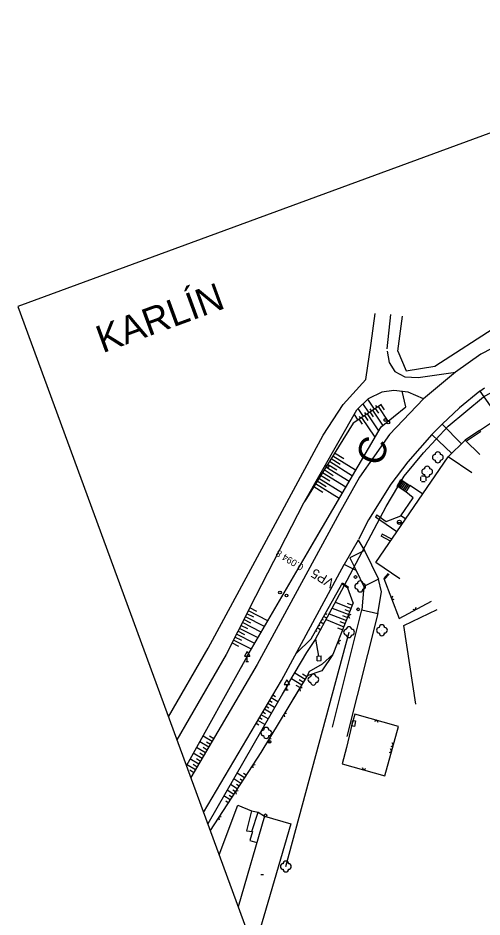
# Model space of a CAD drawing. Extents: x -574526 to -573537, y -1188297 to -1187280.
# Drawn here: x -574525.7 to -574440.8, y -1188129.5 to -1187965.1 of the extents above; entities that cross this region are included whole.
import ezdxf

# ---------------------------------------------------------------- set-up
doc = ezdxf.new("R2010")
doc.units = 0
for name, color, linetype in [('Vrstva 10', 7, 'Continuous'), ('Vrstva 13', 7, 'Continuous'), ('Vrstva 14', 7, 'Continuous'), ('Vrstva 16', 7, 'Continuous'), ('Vrstva 18', 7, 'Continuous'), ('Vrstva 19', 7, 'Continuous'), ('Vrstva 2', 7, 'Continuous'), ('Vrstva 21', 7, 'Continuous'), ('Vrstva 4', 7, 'Continuous'), ('Vrstva 5', 7, 'Continuous'), ('Vrstva 6', 7, 'Continuous'), ('Vrstva 63', 7, 'Continuous'), ('Vrstva 7', 7, 'Continuous'), ('Vrstva 8', 7, 'Continuous'), ('Vrstva 9', 7, 'Continuous')]:
    doc.layers.add(name, color=color, linetype=linetype)

# ---------------------------------------------------------------- blocks, each defined once
blk = doc.blocks.new('8$110')
at = {"layer": 'Vrstva 6'}
blk.add_line((-0.75, 0), (0.75, 0), dxfattribs=at)
blk.add_circle((0, 0), 0.75, dxfattribs=at)
blk = doc.blocks.new('3$130')
at = {"layer": 'Vrstva 8'}
blk.add_circle((0, 0), 0.001, dxfattribs=at)
for centre, start, end in [((-1, 0), 90, 270), ((0, 1), 0, 180), ((1, 0), 270, 90), ((0, -1), 180, 0)]:
    blk.add_arc(centre, 1, start, end, dxfattribs=at)
blk = doc.blocks.new('4$030')
at = {"layer": 'Vrstva 5'}
blk.add_line((-0.502, -0.008), (0.498, -0.008), dxfattribs=at)
blk = doc.blocks.new('5$270')
at = {"layer": 'Vrstva 6'}
for p, q in [((0, 3.732), (-1, 2)), ((0, 3.732), (1, 2)), ((-1, 2), (1, 2)), ((-0.5, 0), (0.5, 0)), ((0, 0), (0, 2))]:
    blk.add_line(p, q, dxfattribs=at)
blk = doc.blocks.new('6$010')
at = {"layer": 'Vrstva 21'}
blk.add_circle((0, 0), 0.5, dxfattribs=at)
blk = doc.blocks.new('6$091')
at = {"layer": 'Vrstva 21'}
for p, q in [((-1, 0.7), (-1, -0.7)), ((0.7, 1), (-0.7, 1)), ((1, -0.7), (1, 0.7)), ((-0.7, -1), (0.7, -1))]:
    blk.add_line(p, q, dxfattribs=at)
blk = doc.blocks.new('200')
at = {"layer": 'Vrstva 63'}
blk.add_lwpolyline([(0, 0), (210, 0), (210, 297), (0, 297), (0, 0)], close=True, dxfattribs=at)

msp = doc.modelspace()

# ---------------------------------------------------------------- linework, layer by layer
at = {"layer": 'Vrstva 10'}
for p, q in [((-574454.79, -1188036.24), (-574455.46, -1188033.34)), ((-574459.24, -1188035.78), (-574464.41, -1188039.22)), ((-574462.72, -1188035.6), (-574461.57, -1188037.33)), ((-574461.78, -1188034.84), (-574460.57, -1188036.66)), ((-574460.35, -1188035.9), (-574460.07, -1188036.33)), ((-574458.03, -1188038.83), (-574459.81, -1188036.16)), ((-574458.7, -1188036.74), (-574459.31, -1188035.82)), ((-574464.26, -1188037.61), (-574463.57, -1188038.66)), ((-574463.56, -1188036.49), (-574462.57, -1188037.99)), ((-574462.35, -1188037.23), (-574462.07, -1188037.66)), ((-574461.7, -1188038.73), (-574462.31, -1188037.82)), ((-574459.74, -1188040.59), (-574461.81, -1188037.49)), ((-574461.35, -1188036.57), (-574461.07, -1188036.99)), ((-574460.7, -1188038.07), (-574461.31, -1188037.15)), ((-574458.97, -1188039.58), (-574460.81, -1188036.82)), ((-574459.7, -1188037.4), (-574460.31, -1188036.49)), ((-574459.32, -1188039.86), (-574454.79, -1188036.24)), ((-574464.41, -1188039.22), (-574473.28, -1188053.46)), ((-574463.35, -1188037.9), (-574463.06, -1188038.33)), ((-574462.69, -1188039.4), (-574463.3, -1188038.49)), ((-574460.42, -1188041.74), (-574462.81, -1188038.15)), ((-574472.34, -1188062.16), (-574459.32, -1188039.86)), ((-574466.79, -1188046.77), (-574468.46, -1188045.72)), ((-574463.97, -1188047.82), (-574468.15, -1188045.21)), ((-574466.15, -1188045.75), (-574467.83, -1188044.71)), ((-574465.18, -1188049.89), (-574469.41, -1188047.25)), ((-574467.42, -1188047.79), (-574469.1, -1188046.74)), ((-574464.57, -1188048.86), (-574468.78, -1188046.23)), ((-574466.39, -1188051.97), (-574470.68, -1188049.29)), ((-574468.69, -1188049.82), (-574470.37, -1188048.78)), ((-574465.78, -1188050.93), (-574470.05, -1188048.27)), ((-574468.06, -1188048.8), (-574469.73, -1188047.76)), ((-574469.96, -1188051.86), (-574471.63, -1188050.82)), ((-574466.99, -1188053), (-574471.32, -1188050.31)), ((-574469.33, -1188050.84), (-574471, -1188049.8)), ((-574483.31, -1188072.98), (-574473.46, -1188053.77)), ((-574472.34, -1188062.16), (-574470.39, -1188058.82)), ((-574483.86, -1188081.95), (-574472.34, -1188062.16)), ((-574483.86, -1188081.95), (-574472.34, -1188062.16)), ((-574472.11, -1188078.6), (-574466.48, -1188068.63)), ((-574471.33, -1188078.7), (-574466.04, -1188068.94)), ((-574464.39, -1188072.03), (-574465.38, -1188069.39)), ((-574467.66, -1188071.93), (-574464.79, -1188073.06)), ((-574465.51, -1188072.13), (-574464.57, -1188072.5)), ((-574483.31, -1188072.98), (-574487.68, -1188081.5)), ((-574480.02, -1188075.35), (-574483.59, -1188073.52)), ((-574482.07, -1188073.62), (-574483.31, -1188072.98)), ((-574482.07, -1188073.62), (-574483.31, -1188072.98)), ((-574468.24, -1188073), (-574465.23, -1188074.18)), ((-574465.95, -1188073.25), (-574465.01, -1188073.62)), ((-574483.17, -1188075.75), (-574484.41, -1188075.12)), ((-574483.17, -1188075.75), (-574484.41, -1188075.12)), ((-574480.62, -1188076.39), (-574484.13, -1188074.58)), ((-574482.62, -1188074.69), (-574483.86, -1188074.05)), ((-574482.62, -1188074.69), (-574483.86, -1188074.05)), ((-574469.8, -1188075.93), (-574470.41, -1188075.59)), ((-574469.85, -1188075.21), (-574470.11, -1188075.07)), ((-574469.25, -1188074.86), (-574469.82, -1188074.54)), ((-574469.26, -1188074.17), (-574469.52, -1188074.02)), ((-574469.39, -1188075.12), (-574466.11, -1188076.41)), ((-574468.81, -1188074.06), (-574465.67, -1188075.29)), ((-574466.83, -1188075.48), (-574465.89, -1188075.85)), ((-574466.39, -1188074.37), (-574465.45, -1188074.73)), ((-574484.26, -1188077.89), (-574485.5, -1188077.25)), ((-574484.26, -1188077.89), (-574485.5, -1188077.25)), ((-574481.83, -1188078.46), (-574485.23, -1188076.72)), ((-574483.71, -1188076.82), (-574484.95, -1188076.19)), ((-574483.71, -1188076.82), (-574484.95, -1188076.19)), ((-574481.23, -1188077.42), (-574484.68, -1188075.65)), ((-574471.03, -1188077.3), (-574471.3, -1188077.15)), ((-574470.39, -1188076.97), (-574471, -1188076.63)), ((-574470.44, -1188076.26), (-574470.71, -1188076.11)), ((-574467.27, -1188076.6), (-574466.33, -1188076.97)), ((-574483.04, -1188080.54), (-574486.32, -1188078.86)), ((-574484.81, -1188078.96), (-574486.05, -1188078.32)), ((-574484.81, -1188078.96), (-574486.05, -1188078.32)), ((-574482.43, -1188079.5), (-574485.78, -1188077.79)), ((-574472.11, -1188078.6), (-574474.8, -1188081.24)), ((-574472.91, -1188081.13), (-574471.32, -1188078.73)), ((-574472.91, -1188081.13), (-574471.32, -1188078.73)), ((-574471.33, -1188078.7), (-574470.79, -1188081.77)), ((-574485.36, -1188080.02), (-574486.6, -1188079.39)), ((-574487.68, -1188081.5), (-574496.66, -1188097.11)), ((-574483.86, -1188081.95), (-574494.94, -1188101.79)), ((-574483.86, -1188081.95), (-574484.91, -1188083.83)), ((-574476.2, -1188086.67), (-574472.91, -1188081.13)), ((-574470.06, -1188083.2), (-574468.12, -1188081.52)), ((-574472.47, -1188084.63), (-574470.06, -1188083.2)), ((-574475.12, -1188084.85), (-574473.21, -1188086.01)), ((-574475.12, -1188084.85), (-574473.21, -1188086.01)), ((-574473.67, -1188085.03), (-574472.9, -1188085.5)), ((-574473.67, -1188085.03), (-574472.9, -1188085.5)), ((-574472.47, -1188084.63), (-574472.86, -1188085.44)), ((-574472.47, -1188084.63), (-574472.86, -1188085.44)), ((-574476.2, -1188086.67), (-574491.03, -1188112.44)), ((-574476.2, -1188086.67), (-574477.4, -1188088.75)), ((-574475.73, -1188085.89), (-574473.83, -1188087.04)), ((-574475.73, -1188085.89), (-574473.83, -1188087.04)), ((-574474.91, -1188087.09), (-574474.14, -1188087.55)), ((-574474.91, -1188087.09), (-574474.14, -1188087.55)), ((-574474.29, -1188086.06), (-574473.52, -1188086.53)), ((-574474.29, -1188086.06), (-574473.52, -1188086.53)), ((-574479.22, -1188090.25), (-574479.72, -1188089.96)), ((-574478.21, -1188090.16), (-574479.42, -1188089.44)), ((-574478.61, -1188089.22), (-574479.11, -1188088.93)), ((-574480.44, -1188092.32), (-574480.94, -1188092.03)), ((-574479.41, -1188092.24), (-574480.64, -1188091.51)), ((-574479.83, -1188091.29), (-574480.33, -1188090.99)), ((-574478.81, -1188091.2), (-574480.03, -1188090.48)), ((-574480.6, -1188094.32), (-574481.86, -1188093.58)), ((-574481.05, -1188093.35), (-574481.55, -1188093.06)), ((-574480, -1188093.28), (-574481.25, -1188092.54)), ((-574481.66, -1188094.39), (-574482.16, -1188094.09)), ((-574491.88, -1188096.38), (-574490.23, -1188097.35)), ((-574490.68, -1188096.39), (-574489.93, -1188096.83)), ((-574493.09, -1188098.45), (-574491.45, -1188099.42)), ((-574492.48, -1188097.42), (-574490.84, -1188098.38)), ((-574491.89, -1188098.46), (-574491.14, -1188098.9)), ((-574491.28, -1188097.43), (-574490.53, -1188097.87)), ((-574493.7, -1188099.49), (-574492.05, -1188100.45)), ((-574492.5, -1188099.5), (-574491.75, -1188099.94)), ((-574494.91, -1188101.56), (-574493.27, -1188102.52)), ((-574494.31, -1188100.52), (-574492.66, -1188101.49)), ((-574493.71, -1188101.57), (-574492.96, -1188102.01)), ((-574493.11, -1188100.53), (-574492.36, -1188100.97)), ((-574494.32, -1188102.6), (-574493.57, -1188103.04)), ((-574485.67, -1188103.13), (-574484.32, -1188104)), ((-574484.47, -1188103.19), (-574484, -1188103.5)), ((-574486.87, -1188105.21), (-574485.63, -1188106.01)), ((-574486.27, -1188104.17), (-574484.98, -1188105.01)), ((-574485.77, -1188105.2), (-574485.3, -1188105.51)), ((-574485.12, -1188104.2), (-574484.65, -1188104.5)), ((-574487.47, -1188106.25), (-574486.28, -1188107.02)), ((-574486.43, -1188106.21), (-574485.96, -1188106.52)), ((-574488.07, -1188107.29), (-574486.94, -1188108.03)), ((-574487.73, -1188108.22), (-574487.26, -1188108.53)), ((-574487.08, -1188107.22), (-574486.61, -1188107.52))]:
    msp.add_line(p, q, dxfattribs=at)
at = {"layer": 'Vrstva 16'}
for p, q in [((-574464.67, -1188094.54), (-574464.46, -1188093.56)), ((-574464.46, -1188093.56), (-574463.98, -1188093.65)), ((-574463.98, -1188093.65), (-574464.17, -1188094.63)), ((-574464.17, -1188094.63), (-574464.67, -1188094.54))]:
    msp.add_line(p, q, dxfattribs=at)
at = {"layer": 'Vrstva 2'}
msp.add_lwpolyline([(-574466.04, -1188068.94), (-574458.4, -1188054.44), (-574455.1, -1188048.91), (-574451.58, -1188044.6), (-574447.05, -1188039.72), (-574440.59, -1188034.41), (-574436.57, -1188032.11), (-574433.45, -1188030.75)], dxfattribs=at)
at = {"layer": 'Vrstva 4'}
for p, q in [((-574456.25, -1188026.01), (-574455.42, -1188019.62)), ((-574449.5, -1188028.77), (-574437.95, -1188021.35)), ((-574490.97, -1188080.36), (-574479.05, -1188058.36)), ((-574455.18, -1188076.22), (-574449.08, -1188073.26)), ((-574452.96, -1188090.57), (-574455.18, -1188076.22)), ((-574476.74, -1188120.25), (-574465.18, -1188077.41)), ((-574498.2, -1188092.91), (-574490.97, -1188080.36))]:
    msp.add_line(p, q, dxfattribs=at)
msp.add_lwpolyline([(-574456.25, -1188026.01), (-574454.72, -1188029.66), (-574449.5, -1188028.77)], dxfattribs=at)
at = {"layer": 'Vrstva 6'}
for p, q in [((-574441.31, -1188040.56), (-574438.57, -1188038.71)), ((-574441.31, -1188040.56), (-574443.92, -1188042.29)), ((-574441.14, -1188040.81), (-574443.7, -1188042.51)), ((-574441.31, -1188040.56), (-574441.14, -1188040.81)), ((-574456.38, -1188050.69), (-574455.68, -1188049.5)), ((-574454.81, -1188051.78), (-574456.38, -1188050.69)), ((-574455.31, -1188049.75), (-574456.1, -1188050.88)), ((-574455.07, -1188049.91), (-574455.86, -1188051.05)), ((-574455.68, -1188049.5), (-574454.05, -1188050.6)), ((-574454.82, -1188050.08), (-574455.61, -1188051.23)), ((-574454.57, -1188050.25), (-574455.36, -1188051.4)), ((-574454.32, -1188050.42), (-574455.12, -1188051.57)), ((-574454.05, -1188050.6), (-574454.81, -1188051.78)), ((-574459.11, -1188059.51), (-574459.29, -1188059.88)), ((-574457.61, -1188060.78), (-574459.29, -1188059.88)), ((-574457.37, -1188060.43), (-574459.11, -1188059.51)), ((-574457.99, -1188066.71), (-574458.83, -1188067.59)), ((-574457.82, -1188066.81), (-574458.68, -1188067.73)), ((-574466.48, -1188068.63), (-574466.37, -1188068.46)), ((-574466.43, -1188068.66), (-574466.48, -1188068.63)), ((-574465.38, -1188069.39), (-574466.43, -1188068.66)), ((-574465.27, -1188069.23), (-574466.37, -1188068.46)), ((-574458.83, -1188067.59), (-574456, -1188074.91)), ((-574458.83, -1188067.59), (-574458.68, -1188067.73)), ((-574465.38, -1188069.39), (-574465.27, -1188069.23)), ((-574464.39, -1188072.03), (-574468.12, -1188081.52)), ((-574456, -1188074.91), (-574450.1, -1188071.73)), ((-574470.98, -1188081.79), (-574470.29, -1188081.73)), ((-574470.98, -1188082.66), (-574470.98, -1188081.79)), ((-574470.29, -1188082.6), (-574470.29, -1188081.73)), ((-574468.12, -1188081.52), (-574470.18, -1188084.45)), ((-574470.98, -1188082.66), (-574470.29, -1188082.6)), ((-574472.83, -1188085.39), (-574481.32, -1188099.38)), ((-574472.83, -1188085.39), (-574475.59, -1188089.93)), ((-574470.18, -1188084.45), (-574472.83, -1188085.39)), ((-574464.09, -1188092.4), (-574464.64, -1188094.38)), ((-574456.1, -1188094.64), (-574464.09, -1188092.4)), ((-574464.64, -1188094.38), (-574465.65, -1188098.5)), ((-574458.61, -1188103.68), (-574456.1, -1188094.64)), ((-574457.99, -1188101.46), (-574456.1, -1188094.64)), ((-574465.65, -1188098.5), (-574466.42, -1188101.49)), ((-574481.32, -1188099.38), (-574490.59, -1188113.65)), ((-574466.42, -1188101.49), (-574458.61, -1188103.68))]:
    msp.add_line(p, q, dxfattribs=at)
for points in [[(-574457.21, -1188070.8), (-574457.42, -1188071.25), (-574456.96, -1188071.45)], [(-574453.52, -1188073.18), (-574453.05, -1188073.32), (-574452.91, -1188072.85)], [(-574464.87, -1188074.2), (-574465.32, -1188074.4), (-574465.12, -1188074.86)], [(-574466.73, -1188078.95), (-574467.19, -1188079.15), (-574466.99, -1188079.6)], [(-574473.76, -1188087.6), (-574474.24, -1188087.72), (-574474.13, -1188088.2)], [(-574473.73, -1188087.54), (-574474.21, -1188087.66), (-574474.09, -1188088.14)], [(-574476.59, -1188092.27), (-574477.08, -1188092.39), (-574476.96, -1188092.87)], [(-574459.85, -1188093.95), (-574460.09, -1188093.52), (-574460.53, -1188093.76)], [(-574479.42, -1188096.93), (-574479.91, -1188097.05), (-574479.79, -1188097.53)], [(-574457.48, -1188098.29), (-574457.05, -1188098.05), (-574457.29, -1188097.62)], [(-574457.79, -1188099.4), (-574457.35, -1188099.16), (-574457.6, -1188098.73)], [(-574482.38, -1188101.65), (-574482.86, -1188101.76), (-574482.76, -1188102.24)], [(-574462.76, -1188102.15), (-574462.52, -1188102.58), (-574462.08, -1188102.34)], [(-574485.47, -1188106.41), (-574485.95, -1188106.51), (-574485.85, -1188107)], [(-574488.56, -1188111.17), (-574489.04, -1188111.27), (-574488.94, -1188111.75)]]:
    msp.add_lwpolyline(points, dxfattribs=at)
at = {"layer": 'Vrstva 7'}
for p, q in [((-574447.01, -1188045.36), (-574443.92, -1188042.29)), ((-574441.27, -1188044.95), (-574443.92, -1188042.29)), ((-574460.27, -1188064.65), (-574447.01, -1188045.36)), ((-574442.73, -1188048.3), (-574447.01, -1188045.36)), ((-574455.89, -1188067.66), (-574460.27, -1188064.65)), ((-574480.65, -1188111.08), (-574485.46, -1188127.6)), ((-574480.65, -1188111.08), (-574475.82, -1188112.43)), ((-574475.82, -1188112.43), (-574481.93, -1188133.39))]:
    msp.add_line(p, q, dxfattribs=at)
at = {"layer": 'Vrstva 9'}
for p, q in [((-574461.11, -1188024.57), (-574460.41, -1188019.13)), ((-574458.19, -1188025.63), (-574457.5, -1188019.35)), ((-574462.1, -1188031.23), (-574461.11, -1188024.57)), ((-574466.25, -1188035.79), (-574462.1, -1188031.23)), ((-574452.54, -1188030.87), (-574445.67, -1188029.88)), ((-574441.24, -1188033.33), (-574440.39, -1188032.74)), ((-574441.24, -1188033.33), (-574438.61, -1188037.07)), ((-574469.93, -1188041.39), (-574466.25, -1188035.79)), ((-574473.46, -1188053.77), (-574463.77, -1188036.75)), ((-574448.16, -1188039.38), (-574450.03, -1188041.26)), ((-574448.16, -1188039.38), (-574444.59, -1188042.95)), ((-574479.05, -1188058.36), (-574469.93, -1188041.39)), ((-574446.38, -1188044.73), (-574450.03, -1188041.26)), ((-574451.71, -1188052.12), (-574454.05, -1188050.6)), ((-574453.46, -1188052.83), (-574454.81, -1188051.78)), ((-574455.71, -1188056.14), (-574453.46, -1188052.83)), ((-574466.91, -1188055.57), (-574482.01, -1188083.33)), ((-574460.06, -1188055.95), (-574460.32, -1188056.36)), ((-574456.42, -1188059.04), (-574460.32, -1188056.36)), ((-574460.06, -1188055.95), (-574458.36, -1188057.15)), ((-574458.36, -1188057.15), (-574455.71, -1188056.14)), ((-574454.87, -1188056.71), (-574455.71, -1188056.14)), ((-574463.53, -1188060.56), (-574466.04, -1188065.03)), ((-574463.53, -1188060.56), (-574462.37, -1188062.48)), ((-574462.37, -1188062.48), (-574465.01, -1188063.82)), ((-574462.37, -1188062.48), (-574459.8, -1188067.75)), ((-574465.01, -1188063.82), (-574463.9, -1188066.15)), ((-574477.51, -1188086.22), (-574466.04, -1188065.03)), ((-574463.9, -1188066.15), (-574466.04, -1188065.03)), ((-574463.9, -1188066.15), (-574462.44, -1188069.09)), ((-574459.8, -1188067.75), (-574462.44, -1188069.09)), ((-574462.44, -1188069.09), (-574462.84, -1188073.31)), ((-574468.2, -1188094.77), (-574462.84, -1188073.31)), ((-574459.91, -1188073.97), (-574465.55, -1188096.51)), ((-574462.84, -1188073.31), (-574459.91, -1188073.97)), ((-574482.01, -1188083.33), (-574494.13, -1188104)), ((-574482.01, -1188083.33), (-574483.02, -1188085.06)), ((-574491.79, -1188110.37), (-574477.51, -1188086.22)), ((-574488.95, -1188118.1), (-574485.53, -1188109.02)), ((-574485.53, -1188109.02), (-574483, -1188110.07)), ((-574483, -1188110.07), (-574483.95, -1188113.71)), ((-574483, -1188110.07), (-574481.81, -1188110.31)), ((-574482.93, -1188113.85), (-574481.81, -1188110.31)), ((-574481.81, -1188110.31), (-574480.65, -1188111.08)), ((-574483.31, -1188115.47), (-574482.04, -1188115.85))]:
    msp.add_line(p, q, dxfattribs=at)
for points in [[(-574435.01, -1188023.49), (-574441.08, -1188026.6), (-574445.67, -1188029.88), (-574451.55, -1188034.72), (-574457.77, -1188041.29), (-574463.27, -1188049.05), (-574466.91, -1188055.57)], [(-574458.22, -1188026.03), (-574457.85, -1188028.09), (-574456.82, -1188029.76), (-574454.94, -1188030.75), (-574452.54, -1188030.87)], [(-574451.55, -1188034.72), (-574454.33, -1188033.52), (-574456.96, -1188033.23), (-574459.16, -1188033.55), (-574461.65, -1188034.73), (-574463.77, -1188036.75)], [(-574441.24, -1188033.33), (-574444.97, -1188036.42), (-574448.16, -1188039.38)], [(-574450.03, -1188041.26), (-574454.39, -1188046.24), (-574457.54, -1188050.37), (-574461.64, -1188056.88), (-574463.47, -1188060.47)], [(-574459.91, -1188073.97), (-574459.23, -1188070.05), (-574459.8, -1188067.75)], [(-574483.95, -1188113.71), (-574482.84, -1188113.86), (-574483.31, -1188115.47)]]:
    msp.add_lwpolyline(points, dxfattribs=at)

# ---------------------------------------------------------------- block references
at = {"layer": 'Vrstva 21', "xscale": 0.5, "yscale": 0.5}
for name, p in [('6$010', (-574458.55, -1188038.62)), ('6$010', (-574457.99, -1188039.09)), ('6$010', (-574469.14, -1188047.07)), ('6$091', (-574451.59, -1188049.38)), ('6$010', (-574464.01, -1188067.33)), ('6$010', (-574477.81, -1188070.14)), ('6$010', (-574476.62, -1188070.73)), ('6$010', (-574463.53, -1188073.23)), ('6$010', (-574479.72, -1188097.48)), ('6$010', (-574480.47, -1188110.9))]:
    msp.add_blockref(name, p, dxfattribs=at)
at = {"layer": 'Vrstva 4', "xscale": 0.5, "yscale": 0.5}
for p in [(-574448.93, -1188045.45), (-574450.88, -1188048.07), (-574463.14, -1188069.05), (-574465.18, -1188077.41), (-574459.16, -1188077.05), (-574471.7, -1188086.08), (-574480.32, -1188095.83), (-574476.74, -1188120.25)]:
    msp.add_blockref('3$130', p, dxfattribs=at)
at = {"layer": 'Vrstva 5', "xscale": 0.5, "yscale": 0.5}
msp.add_blockref('4$030', (-574481.09, -1188121.73), dxfattribs=at)
at = {"layer": 'Vrstva 6', "xscale": 0.5, "yscale": 0.5}
for name, p in [('8$110', (-574455.96, -1188057.33)), ('5$270', (-574483.82, -1188082.8)), ('5$270', (-574476.55, -1188087.97))]:
    msp.add_blockref(name, p, dxfattribs=at)
at = {"layer": 'Vrstva 63', "xscale": 2.9999999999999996, "rotation": 20.160475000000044}
msp.add_blockref('200', (-574423.39, -1188296.69), dxfattribs=at)

# ---------------------------------------------------------------- texts
at = {"layer": 'Vrstva 13'}
msp.add_text('0.094 8', height=1.25, rotation=148.3356, dxfattribs=at).set_placement((-574473.35, -1188065.19))
at = {"layer": 'Vrstva 14'}
msp.add_text('C', height=5, rotation=71.5717, dxfattribs=at).set_placement((-574459.3, -1188047.27))
at = {"layer": 'Vrstva 18'}
msp.add_text('VP5', height=1.75, rotation=148.3356, dxfattribs=at).set_placement((-574467.67, -1188067.99))
at = {"layer": 'Vrstva 19'}
msp.add_text('KARLÍN', height=4.999, rotation=20.1605, dxfattribs=at).set_placement((-574510.27, -1188026.43))

doc.saveas('drawing.dxf')
